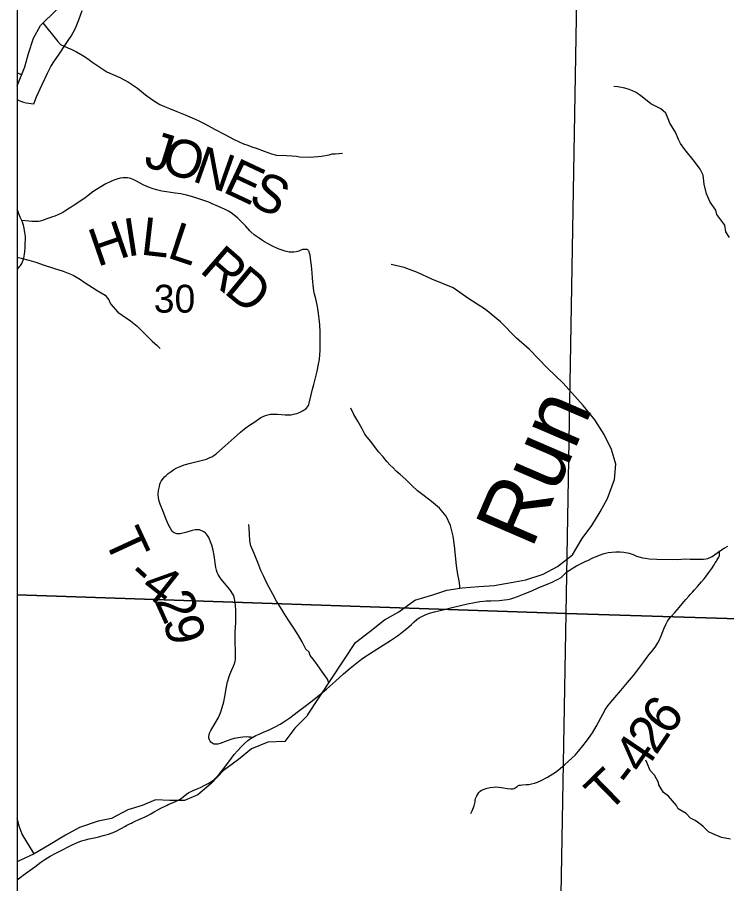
# Model space of a CAD drawing. Extents: x 6.3 to 40.3, y 9 to 31.
# Drawn here: x 8.445 to 9.509, y 23.853 to 25.154 of the extents above; entities that cross this region are included whole.
import ezdxf

# ---------------------------------------------------------------- set-up
doc = ezdxf.new("R2010")
doc.units = 0
for name, color, linetype in [('Default', 7, 'Continuous'), ('GM_X_Corporation', 7, 'Continuous'), ('GM_X_County_Road', 7, 'Continuous'), ('GM_X_Minor_River', 7, 'Continuous'), ('GM_X_Minor_River_Text', 7, 'Continuous'), ('GM_X_Section', 7, 'Continuous'), ('GM_X_Section_Text', 7, 'Continuous'), ('GM_X_Township_Road', 7, 'Continuous'), ('GM_X_Township_Road_Text', 7, 'Continuous'), ('SH_Cut_Line', 7, 'Continuous'), ('SH_Data', 7, 'Continuous')]:
    doc.layers.add(name, color=color, linetype=linetype)

msp = doc.modelspace()

# ---------------------------------------------------------------- linework, layer by layer
at = {"layer": 'Default'}
for points in [[(12.9672, 29.1426), (12.4918, 29.1593), (11.6221, 29.1933), (10.6176, 29.225), (10.0496, 29.2462), (9.8361, 29.2507), (8.8673, 29.2829), (8.4446, 29.2958), (8.4446, 23.1457)], [(12.5872, 27.7766), (11.7175, 27.8106), (10.7129, 27.8423), (10.145, 27.8635), (9.9314, 27.8681), (8.9627, 27.9002), (8.4446, 27.9161), (8.4446, 23.1457)]]:
    msp.add_lwpolyline(points, dxfattribs=at)
at = {"layer": 'GM_X_Corporation'}
for points in [[(8.4446, 25.2858), (8.4446, 24.2863), (9.2683, 24.2583), (9.286, 25.2685)], [(8.4446, 24.2863), (8.4446, 23.273), (9.2503, 23.246), (9.2683, 24.2583)]]:
    msp.add_lwpolyline(points, close=True, dxfattribs=at)
at = {"layer": 'GM_X_County_Road'}
for points in [[(8.4693, 25.0235), (8.4736, 25.0344), (8.4818, 25.0527), (8.4863, 25.0622), (8.4899, 25.07), (8.4951, 25.0799), (8.5004, 25.0882), (8.5062, 25.097), (8.518, 25.1145), (8.5208, 25.1187), (8.5252, 25.1254), (8.5284, 25.1308), (8.5312, 25.1364), (8.5337, 25.1421), (8.5367, 25.1497), (8.5419, 25.1636)], [(8.4513, 24.8484), (8.449, 24.8535), (8.447, 24.8587), (8.445, 24.8645), (8.4446, 24.8658)], [(8.4446, 24.7752), (8.4452, 24.7759), (8.448, 24.7793), (8.4493, 24.7811), (8.4512, 24.7841), (8.4523, 24.7866), (8.4532, 24.789), (8.4542, 24.7918), (8.4548, 24.795), (8.4553, 24.798), (8.4559, 24.802), (8.4562, 24.8078), (8.4566, 24.8134), (8.4569, 24.8203), (8.4568, 24.8247), (8.4561, 24.8303), (8.455, 24.8371), (8.4541, 24.8414), (8.4531, 24.8444), (8.4513, 24.8484)]]:
    msp.add_lwpolyline(points, dxfattribs=at)
at = {"layer": 'GM_X_Minor_River'}
msp.add_line((8.4511, 25.0671), (8.4446, 25.0705), dxfattribs=at)
for points in [[(8.4446, 25.0506), (8.4559, 25.0792), (8.4612, 25.0992), (8.4688, 25.1223), (8.4794, 25.1415), (8.5036, 25.1649)], [(8.4831, 25.1451), (8.5053, 25.1172), (8.5096, 25.1127), (8.5202, 25.1079), (8.5263, 25.1053), (8.5336, 25.102), (8.5428, 25.0964), (8.5512, 25.0908), (8.5565, 25.0866), (8.5791, 25.0717), (8.5982, 25.0635), (8.6112, 25.0561), (8.6249, 25.0471), (8.6372, 25.037), (8.6475, 25.0295), (8.6544, 25.025), (8.6586, 25.0228), (8.6655, 25.0195), (8.6731, 25.0165), (8.6842, 25.0121), (8.6964, 25.0073), (8.7071, 25.0028), (8.7158, 24.9987), (8.7258, 24.9935), (8.7403, 24.9857), (8.7559, 24.9775), (8.7689, 24.9708), (8.7777, 24.9668), (8.7842, 24.9638), (8.7903, 24.9616), (8.7964, 24.9594), (8.8044, 24.9564), (8.8151, 24.9527), (8.8261, 24.9487), (8.8337, 24.9468), (8.8486, 24.9462), (8.8573, 24.9456), (8.8638, 24.9449), (8.8679, 24.9442), (8.8839, 24.9436), (8.901, 24.9449), (8.9127, 24.9473), (8.9173, 24.9485), (8.9214, 24.9485), (8.9328, 24.9494)], [(9.5136, 24.8228), (9.5079, 24.8314), (9.5066, 24.8413), (9.4943, 24.8575), (9.4927, 24.8639), (9.4842, 24.876), (9.4791, 24.8888), (9.4752, 24.9032), (9.4739, 24.9165), (9.4696, 24.9256), (9.4608, 24.9369), (9.4465, 24.9553), (9.44, 24.964), (9.4369, 24.9704), (9.4326, 24.9814), (9.4237, 24.9949), (9.4214, 25.001), (9.4178, 25.0097), (9.4102, 25.0164), (9.3953, 25.0239), (9.3823, 25.034), (9.3781, 25.0374), (9.3723, 25.0411), (9.3677, 25.0433), (9.3628, 25.0452), (9.3563, 25.047), (9.3457, 25.0492), (9.3396, 25.0499)], [(8.4446, 24.7934), (8.4504, 24.792), (8.4618, 24.7891), (8.4724, 24.7858), (8.485, 24.7817), (8.4991, 24.777), (8.5136, 24.7726), (8.5285, 24.7663), (8.5392, 24.7599), (8.5449, 24.7558), (8.5644, 24.7435), (8.5763, 24.7364), (8.5817, 24.7292), (8.5844, 24.7236), (8.5955, 24.7108), (8.602, 24.7063), (8.6143, 24.6981), (8.6242, 24.6898), (8.6327, 24.6819), (8.6403, 24.6741), (8.6476, 24.6669), (8.6538, 24.6613), (8.6591, 24.6564)], [(8.8802, 24.106), (8.9523, 24.215), (8.9738, 24.2316), (8.9958, 24.249), (9.017, 24.2611), (9.0412, 24.2784), (9.0681, 24.2867), (9.0893, 24.2935), (9.1124, 24.2969), (9.137, 24.2988), (9.1601, 24.3003), (9.1858, 24.3049), (9.2078, 24.309), (9.2339, 24.3173), (9.2551, 24.329), (9.2778, 24.3464), (9.2922, 24.3709), (9.307, 24.3905), (9.3195, 24.4109), (9.3304, 24.4309), (9.341, 24.4596), (9.3429, 24.4826), (9.3361, 24.5045), (9.3255, 24.5272), (9.3111, 24.5491), (9.2937, 24.5706), (9.2638, 24.6045), (9.2396, 24.6275), (9.2134, 24.6551), (9.1937, 24.6717), (9.1695, 24.6962), (9.1472, 24.7151), (9.1222, 24.7309), (9.0987, 24.7472), (9.0669, 24.7604), (9.045, 24.7706), (9.0253, 24.7781), (9.0056, 24.7826)], [(9.1087, 24.2966), (9.1088, 24.3002), (9.1076, 24.3077), (9.1056, 24.3168), (9.1039, 24.3305), (9.1005, 24.3601), (9.0985, 24.3748), (9.0949, 24.3904), (9.0883, 24.4047), (9.0783, 24.4164), (9.0664, 24.4265), (9.0553, 24.4351), (9.0454, 24.4426), (9.0365, 24.4509), (9.0277, 24.4599), (9.0193, 24.4674), (9.0131, 24.4723), (9.0085, 24.4771), (9.0043, 24.4813), (8.9993, 24.4869), (8.9935, 24.4937), (8.987, 24.5008), (8.9808, 24.5091), (8.9751, 24.5167), (8.9697, 24.5231), (8.9662, 24.5276), (8.9619, 24.5355), (8.9554, 24.5472), (8.9496, 24.5574), (8.9449, 24.5668)], [(8.9123, 24.1546), (8.9102, 24.1598), (8.9001, 24.1741), (8.8947, 24.182), (8.8886, 24.19), (8.884, 24.1956), (8.8828, 24.2005), (8.8778, 24.205), (8.872, 24.216), (8.8666, 24.2254), (8.8596, 24.2363), (8.8527, 24.2469), (8.8461, 24.2571), (8.8399, 24.2669), (8.8337, 24.2771), (8.8279, 24.2873), (8.8225, 24.2975), (8.8178, 24.3061), (8.8143, 24.3141), (8.8101, 24.3231), (8.8054, 24.3352), (8.7999, 24.3485), (8.7952, 24.3602), (8.7933, 24.3674), (8.7928, 24.3776), (8.7923, 24.386), (8.7922, 24.3921)], [(8.8799, 24.1055), (8.861, 24.0861), (8.8463, 24.0664), (8.8206, 24.0653), (8.796, 24.0554), (8.7763, 24.0395), (8.754, 24.0228), (8.7355, 24.0031), (8.7154, 23.986), (8.6954, 23.9777), (8.6734, 23.9777), (8.6519, 23.9788), (8.6318, 23.9701), (8.6106, 23.9637), (8.586, 23.9508), (8.566, 23.9466), (8.538, 23.9371), (8.5168, 23.9257), (8.493, 23.9113), (8.4701, 23.8977), (8.4484, 23.8875), (8.4446, 23.8854)], [(9.5149, 23.9194), (9.5015, 23.9223), (9.4883, 23.9276), (9.4818, 23.9304), (9.4738, 23.9388), (9.4707, 23.941), (9.4617, 23.9479), (9.4551, 23.9511), (9.4483, 23.958), (9.4366, 23.9652), (9.4341, 23.9704), (9.4217, 23.9844), (9.4146, 23.9895), (9.4102, 23.9962), (9.4073, 24.0014), (9.4067, 24.0048), (9.4009, 24.0156), (9.3945, 24.0226), (9.3899, 24.0335), (9.3879, 24.0384)], [(8.4694, 23.898), (8.4701, 23.8977), (8.4521, 23.9271), (8.4474, 23.9393), (8.4446, 23.9505)]]:
    msp.add_lwpolyline(points, dxfattribs=at)
at = {"layer": 'GM_X_Section'}
msp.add_lwpolyline([(9.286, 25.2685), (10.2864, 25.2447), (10.2678, 24.2273), (9.2683, 24.2583)], close=True, dxfattribs=at)
msp.add_lwpolyline([(9.2503, 23.246), (9.2683, 24.2583), (10.2678, 24.2273), (10.2651, 24.0807), (10.2532, 24.0699), (10.2424, 24.0573), (10.2324, 24.045), (10.2126, 24.0223), (10.1932, 24.0046), (10.1738, 23.9838), (10.1615, 23.973), (10.1379, 23.9548), (10.1264, 23.9425), (10.1134, 23.9241), (10.1074, 23.9183), (10.0915, 23.893), (10.0745, 23.867), (10.0585, 23.8459)], dxfattribs=at)
at = {"layer": 'GM_X_Township_Road'}
for points in [[(8.4446, 25.0304), (8.4475, 25.0287), (8.4509, 25.0272), (8.4538, 25.0262), (8.4579, 25.0253), (8.4693, 25.0235)], [(8.8866, 24.7751), (8.8862, 24.7811), (8.8852, 24.7873), (8.8839, 24.7965), (8.8833, 24.7995), (8.8824, 24.8019), (8.8818, 24.803), (8.8813, 24.8038), (8.8806, 24.8043), (8.8797, 24.8048), (8.8787, 24.8051), (8.8774, 24.8052), (8.8759, 24.8052), (8.8746, 24.8051), (8.8727, 24.8048), (8.8692, 24.8036), (8.8669, 24.8027), (8.8633, 24.8017), (8.8596, 24.8011), (8.8571, 24.8009), (8.8548, 24.8009), (8.8527, 24.8011), (8.8504, 24.8015), (8.8468, 24.8024), (8.842, 24.8039), (8.8363, 24.8062), (8.8278, 24.81), (8.8212, 24.8134), (8.8157, 24.8164), (8.811, 24.8193), (8.8059, 24.8228), (8.8, 24.8272), (8.7954, 24.8312), (8.7937, 24.8329), (8.787, 24.8403), (8.7811, 24.8466), (8.7753, 24.8522), (8.7701, 24.8566), (8.7656, 24.8599), (8.7614, 24.8626), (8.7564, 24.8652), (8.7463, 24.8698), (8.7372, 24.8738), (8.7321, 24.8759), (8.7276, 24.8776), (8.7184, 24.8808), (8.7126, 24.8826), (8.7073, 24.8841), (8.699, 24.8865), (8.6942, 24.8876), (8.69, 24.8885), (8.6815, 24.8898), (8.6687, 24.8915), (8.6614, 24.8928), (8.6536, 24.8946), (8.647, 24.8965), (8.6413, 24.8987), (8.6345, 24.9017), (8.6278, 24.905), (8.6236, 24.9076), (8.6193, 24.9098), (8.6148, 24.9116), (8.6101, 24.9126), (8.6065, 24.9128), (8.6035, 24.9128), (8.5987, 24.9121), (8.594, 24.9108), (8.5894, 24.9092), (8.5839, 24.9068), (8.5775, 24.9037), (8.5698, 24.8993), (8.5633, 24.8952), (8.5579, 24.8914), (8.5511, 24.8863), (8.5457, 24.8823), (8.5402, 24.8784), (8.5356, 24.8753), (8.5299, 24.8715), (8.5252, 24.8685), (8.5205, 24.8654), (8.5169, 24.8631), (8.5159, 24.8625), (8.5146, 24.8616), (8.5131, 24.8607), (8.5109, 24.8596), (8.5087, 24.8585), (8.5054, 24.8569), (8.5009, 24.8552), (8.4975, 24.854), (8.4936, 24.8527), (8.4889, 24.851), (8.4823, 24.8485), (8.4791, 24.8476), (8.4762, 24.8471), (8.4732, 24.8468), (8.4701, 24.8469), (8.4665, 24.8471), (8.4617, 24.8475), (8.4513, 24.8484)], [(8.7973, 24.0723), (8.7945, 24.0726), (8.7914, 24.073), (8.7884, 24.0731), (8.783, 24.0727), (8.7758, 24.0719), (8.7698, 24.0708), (8.7651, 24.0695), (8.7594, 24.0675), (8.7491, 24.0635), (8.7456, 24.0625), (8.7432, 24.0621), (8.7414, 24.0622), (8.7396, 24.0625), (8.7379, 24.0632), (8.7364, 24.0641), (8.7351, 24.0654), (8.7339, 24.0668), (8.7329, 24.069), (8.7322, 24.0714), (8.732, 24.0738), (8.7323, 24.0762), (8.7331, 24.0786), (8.7352, 24.0829), (8.7459, 24.1013), (8.7481, 24.1057), (8.7502, 24.1107), (8.7522, 24.1171), (8.7545, 24.1259), (8.7561, 24.1336), (8.7587, 24.1485), (8.7602, 24.1557), (8.7623, 24.164), (8.7633, 24.1669), (8.7663, 24.1737), (8.7688, 24.1793), (8.7705, 24.1833), (8.7716, 24.1868), (8.772, 24.1899), (8.7721, 24.1942), (8.7719, 24.2048), (8.7716, 24.2128), (8.7715, 24.2184), (8.7715, 24.2227), (8.7716, 24.227), (8.7717, 24.2295), (8.7717, 24.2319), (8.7719, 24.2362), (8.7724, 24.2461), (8.7726, 24.2542), (8.7724, 24.2635), (8.7721, 24.2707), (8.7717, 24.2744), (8.7711, 24.2782), (8.7705, 24.2807), (8.7698, 24.283), (8.7688, 24.2859), (8.7672, 24.289), (8.7656, 24.2915), (8.7633, 24.2944), (8.7504, 24.31), (8.7475, 24.3143), (8.7458, 24.3172), (8.7445, 24.32), (8.7434, 24.3235), (8.7427, 24.3275), (8.74, 24.3456), (8.7385, 24.3538), (8.7363, 24.3609), (8.7345, 24.3663), (8.7332, 24.3701), (8.7322, 24.3725), (8.7311, 24.3741), (8.73, 24.3758), (8.7287, 24.3774), (8.7269, 24.3792), (8.7247, 24.381), (8.7223, 24.3823), (8.72, 24.3833), (8.7179, 24.3839), (8.7152, 24.3841), (8.7115, 24.3839), (8.7072, 24.3831), (8.6988, 24.3807), (8.6929, 24.379), (8.6892, 24.3782), (8.6861, 24.3781), (8.6842, 24.3782), (8.6828, 24.3785), (8.6814, 24.3789), (8.6802, 24.3795), (8.6787, 24.3805), (8.6773, 24.3818), (8.6758, 24.3838), (8.6739, 24.3869), (8.6712, 24.3926), (8.6675, 24.4011), (8.6633, 24.4115), (8.6591, 24.4225), (8.6575, 24.4272), (8.6563, 24.4321), (8.6561, 24.437), (8.6567, 24.4431), (8.6578, 24.4492), (8.6586, 24.4528), (8.6595, 24.4552), (8.6606, 24.4573), (8.6641, 24.4616), (8.6657, 24.4635), (8.6679, 24.4656), (8.6711, 24.4685), (8.6755, 24.4719), (8.6796, 24.4747), (8.6839, 24.4771), (8.689, 24.4794), (8.6949, 24.4815), (8.7045, 24.4841), (8.7226, 24.4885), (8.7285, 24.4904), (8.7326, 24.492), (8.7364, 24.4939), (8.7396, 24.4959), (8.7431, 24.4984), (8.7478, 24.5025), (8.7565, 24.5104), (8.77, 24.5223), (8.7793, 24.5305), (8.783, 24.5337), (8.7874, 24.5371), (8.7929, 24.541), (8.801, 24.5464), (8.8065, 24.5503), (8.8101, 24.5527), (8.8133, 24.5545), (8.8168, 24.5559), (8.8203, 24.557), (8.8246, 24.5577), (8.8295, 24.558), (8.835, 24.5578), (8.8467, 24.5568), (8.8517, 24.5568), (8.8554, 24.557), (8.8591, 24.5576), (8.8639, 24.5589), (8.8691, 24.5609), (8.8735, 24.5631), (8.8767, 24.5652), (8.8785, 24.5668), (8.8801, 24.5687), (8.8814, 24.5708), (8.8822, 24.5725), (8.8826, 24.5742), (8.8856, 24.5868), (8.8878, 24.5952), (8.8897, 24.6024), (8.8945, 24.6223), (8.8968, 24.6326), (8.898, 24.6399), (8.8988, 24.6473), (8.8991, 24.6529), (8.8993, 24.6585), (8.8993, 24.6634), (8.8993, 24.667), (8.8993, 24.6711), (8.8992, 24.6767), (8.8992, 24.6813), (8.8987, 24.6917), (8.8978, 24.7009), (8.8967, 24.7089), (8.8949, 24.7193), (8.8924, 24.7309), (8.8907, 24.7381), (8.8898, 24.743), (8.8886, 24.7516), (8.888, 24.7566), (8.8875, 24.7621), (8.8869, 24.7701), (8.8866, 24.7751)], [(8.9219, 24.1567), (8.9343, 24.168), (8.9442, 24.1764), (8.9568, 24.1866), (8.9633, 24.1913), (8.9784, 24.2012), (9.0046, 24.2179), (9.0149, 24.2248), (9.0219, 24.23), (9.032, 24.2382), (9.036, 24.2421), (9.04, 24.246), (9.0443, 24.2496), (9.0479, 24.252), (9.0516, 24.2542), (9.0567, 24.2565), (9.0631, 24.2588), (9.0708, 24.261), (9.0792, 24.2631), (9.0895, 24.2656), (9.0973, 24.2676), (9.1099, 24.2707), (9.1202, 24.273), (9.1306, 24.2751), (9.1385, 24.2765), (9.1441, 24.277), (9.1484, 24.2774), (9.1552, 24.2777), (9.1675, 24.2781), (9.1755, 24.2788), (9.1804, 24.2795), (9.1852, 24.2805), (9.1899, 24.2821), (9.1953, 24.284), (9.2052, 24.2882), (9.2166, 24.2927), (9.2263, 24.2968), (9.2325, 24.2996), (9.2388, 24.3022), (9.2481, 24.306), (9.252, 24.3078), (9.2553, 24.3095), (9.2606, 24.3125), (9.2633, 24.3148), (9.2661, 24.318), (9.2695, 24.3208), (9.2742, 24.3241), (9.2786, 24.3269), (9.2837, 24.3299), (9.2907, 24.3335), (9.294, 24.3351), (9.298, 24.3368), (9.3008, 24.3381), (9.3075, 24.3413), (9.3183, 24.3461), (9.3254, 24.3486), (9.3312, 24.3502), (9.3366, 24.3508), (9.3427, 24.3512), (9.3492, 24.3512), (9.3546, 24.3507), (9.3627, 24.3491), (9.3686, 24.347), (9.3739, 24.3448), (9.3791, 24.343), (9.3828, 24.3421), (9.3872, 24.3413), (9.3929, 24.3404), (9.4044, 24.3399), (9.4353, 24.3397), (9.4472, 24.3404), (9.4542, 24.3402), (9.4606, 24.3402), (9.4661, 24.34), (9.4706, 24.3398), (9.4743, 24.3398), (9.478, 24.3403), (9.4807, 24.3411), (9.4872, 24.3443), (9.4963, 24.3507), (9.4983, 24.352)], [(9.4943, 24.3378), (9.4976, 24.3432), (9.4982, 24.3451), (9.4986, 24.3475), (9.4983, 24.352)], [(9.4983, 24.352), (9.5056, 24.3568), (9.5109, 24.3598)], [(9.13, 23.9695), (9.1306, 23.9715), (9.1315, 23.9758), (9.1317, 23.9782), (9.1323, 23.9806), (9.134, 23.9846), (9.1355, 23.9873), (9.1374, 23.9898), (9.1392, 23.9915), (9.1412, 23.993), (9.144, 23.9943), (9.1475, 23.9955), (9.1541, 23.9971), (9.159, 23.9979), (9.1627, 23.998), (9.167, 23.9977), (9.1743, 23.9965), (9.1797, 23.9956), (9.1853, 23.9952), (9.1883, 23.9953), (9.1901, 23.9957), (9.1917, 23.9966), (9.1942, 23.9984), (9.1957, 23.9995), (9.1979, 24.0005), (9.1997, 24.0009), (9.2028, 24.0013), (9.2084, 24.0016), (9.2121, 24.0019), (9.2164, 24.0025), (9.2206, 24.0036), (9.2252, 24.0053), (9.2308, 24.0079), (9.2401, 24.0129), (9.2482, 24.0176), (9.2523, 24.0203), (9.2563, 24.0234), (9.2662, 24.0316), (9.2767, 24.0411), (9.2816, 24.046), (9.2867, 24.0517), (9.2935, 24.06), (9.299, 24.0667), (9.303, 24.0722), (9.3077, 24.0795), (9.3131, 24.0886), (9.3236, 24.1083), (9.3274, 24.1146), (9.3309, 24.1196), (9.3355, 24.1255), (9.3505, 24.1429), (9.3605, 24.1547), (9.3691, 24.1653), (9.3771, 24.1757), (9.3849, 24.1861), (9.3899, 24.1931), (9.3929, 24.1969), (9.3987, 24.204), (9.4027, 24.2095), (9.4057, 24.2142), (9.4083, 24.2191), (9.4108, 24.2248), (9.4133, 24.2312), (9.4154, 24.2364), (9.4178, 24.242), (9.4204, 24.2469), (9.4228, 24.2504), (9.4259, 24.2541), (9.4312, 24.2601), (9.4348, 24.2641), (9.4477, 24.2797), (9.4523, 24.2846), (9.4548, 24.2873), (9.4577, 24.2905), (9.461, 24.2941), (9.4655, 24.2991), (9.4715, 24.3058), (9.4753, 24.3104), (9.4786, 24.3146), (9.4826, 24.3199), (9.4868, 24.326), (9.4904, 24.3316), (9.492, 24.3343), (9.4938, 24.3369), (9.4943, 24.3378)], [(8.7973, 24.0723), (8.8024, 24.0751), (8.8077, 24.0775), (8.8148, 24.0807), (8.8214, 24.0834), (8.8265, 24.0857), (8.8327, 24.0886), (8.8389, 24.0921), (8.8444, 24.0957), (8.8536, 24.102), (8.8646, 24.1101), (8.8784, 24.1206), (8.8872, 24.1275), (8.8975, 24.1356), (8.9084, 24.1447), (8.9219, 24.1567)], [(8.4446, 23.8588), (8.4485, 23.8617), (8.4536, 23.8654), (8.4711, 23.8782), (8.4798, 23.8849), (8.4861, 23.8892), (8.494, 23.894), (8.5012, 23.8982), (8.5084, 23.9018), (8.5142, 23.9047), (8.5199, 23.9075), (8.5271, 23.9111), (8.5351, 23.9146), (8.5407, 23.9169), (8.5467, 23.9188), (8.5526, 23.9203), (8.5597, 23.9217), (8.567, 23.9232), (8.5735, 23.9249), (8.5812, 23.9271), (8.5883, 23.9297), (8.5939, 23.9321), (8.5994, 23.935), (8.6069, 23.9394), (8.6091, 23.9406), (8.6124, 23.9423), (8.6129, 23.9426), (8.6157, 23.9439), (8.6174, 23.9447), (8.6202, 23.946), (8.627, 23.9491), (8.6366, 23.9532), (8.6404, 23.9552), (8.6448, 23.9576), (8.6502, 23.9606), (8.6556, 23.9636), (8.6599, 23.966), (8.6622, 23.967), (8.6654, 23.9689), (8.6683, 23.9702), (8.6693, 23.9709), (8.6721, 23.9721), (8.6808, 23.9756), (8.6842, 23.9771), (8.6864, 23.9782), (8.6895, 23.9802), (8.6906, 23.9809), (8.6939, 23.9837), (8.6983, 23.9871), (8.7019, 23.9895), (8.7064, 23.9916), (8.7086, 23.9927), (8.7143, 23.9952), (8.7195, 23.9974), (8.7251, 24), (8.7311, 24.0032), (8.7359, 24.0062), (8.7393, 24.0088), (8.743, 24.0121), (8.748, 24.0177), (8.7542, 24.0254), (8.7621, 24.0359), (8.7702, 24.0468), (8.7754, 24.053), (8.7805, 24.0585), (8.7854, 24.0632), (8.7907, 24.0676), (8.7962, 24.0716), (8.7973, 24.0723)], [(9.1253, 23.9584), (9.1273, 23.9622), (9.1294, 23.9674), (9.13, 23.9695)]]:
    msp.add_lwpolyline(points, dxfattribs=at)
at = {"layer": 'SH_Cut_Line'}
msp.add_lwpolyline([(12.9672, 29.1426), (12.4918, 29.1593), (11.6221, 29.1933), (10.6176, 29.225), (10.0496, 29.2462), (9.8361, 29.2507), (8.8673, 29.2829), (8.4446, 29.2958), (8.4446, 23.1457)], dxfattribs=at)
at = {"layer": 'SH_Data'}
msp.add_line((8.4446, 29.9457), (8.4446, 23.1457), dxfattribs=at)

# ---------------------------------------------------------------- texts
at = {"layer": 'GM_X_Minor_River_Text'}
msp.add_text('Run', height=0.09469, rotation=66.6133, dxfattribs=at).set_placement((9.2165, 24.3539))
at = {"layer": 'GM_X_Section_Text'}
msp.add_text('30', height=0.04186, rotation=0, dxfattribs=at).set_placement((8.6494, 24.7102))
at = {"layer": 'GM_X_Township_Road_Text'}
for s, rotation, p in [('J', 342.901, (8.6326, 24.9306)), ('O', 342.8381, (8.6581, 24.9228)), ('N', 340.5576, (8.7053, 24.9082)), ('E', 334.8437, (8.7511, 24.8922)), ('S', 334.4316, (8.7894, 24.8741)), ('H', 18.981, (8.5647, 24.7785)), ('I', 8.8233, (8.6094, 24.7941)), ('L', 353.4502, (8.6284, 24.7976)), ('L', 341.6254, (8.6676, 24.7935)), ('R', 318.994, (8.7167, 24.7723)), ('D', 320.3959, (8.753, 24.7407)), ('T', 294.7632, (8.5739, 24.3707)), ('-', 317.6221, (8.6062, 24.3123)), ('4', 321.7097, (8.6268, 24.2937)), ('2', 294.3524, (8.6499, 24.2776)), ('9', 283.7232, (8.6634, 24.2484)), ('6', 53.1951, (9.4223, 24.0729)), ('2', 55.967, (9.4032, 24.0445)), ('4', 55.8268, (9.3834, 24.0154)), ('T', 44.3167, (9.3309, 23.9576)), ('-', 52.6473, (9.3673, 23.9941))]:
    msp.add_text(s, height=0.0568, rotation=rotation, dxfattribs=at).set_placement(p)

doc.saveas('drawing.dxf')
